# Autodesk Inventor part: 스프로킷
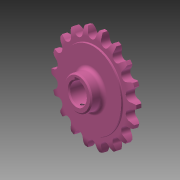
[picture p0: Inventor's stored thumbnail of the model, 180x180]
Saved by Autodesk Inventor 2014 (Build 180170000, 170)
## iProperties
Created: 2016-03
Part Number: 스프로킷
Material: 강철, 탄소
Document SubType Name: Modeling
Designer: mduedu
Density: 7.87 g/cm^3
Mass: 301.818 g
Surface Area: 124.882 cm^2
Volume: 38.3505 cm^3
Appearance: Pink
Author: mduedu
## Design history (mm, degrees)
sketch "스케치1"
  geometry: L1 (0, 5)-(29.5, 5); L2 (29.5, 5)-(29.5, 4.1); L3 (30, 3.6)-(33.625, 3.6); L4 (40, 2)-(40, 0); L5 (40, 0)-(0, 0); L6 (0, 0)-(0, 5); L7 (0, -5)-(29.5, -5); L8 (29.5, -5)-(29.5, -4.1); L9 (30, -3.6)-(33.625, -3.6); L10 (40, -2)-(40, 0); L11 (0, 0)-(0, -5); A1 r 13.5 centre (33.625, -9.9) between (40, 2) and (33.625, 3.6); A2 r 13.5 centre (33.625, 9.9) between (33.625, -3.6) and (40, -2); A3 r 0.5 centre (30, 4.1) between (29.5, 4.1) and (30, 3.6); A4 r 0.5 centre (30, -4.1) between (30, -3.6) and (29.5, -4.1); 2 further points
  constraints: 22 end point, 8 point on circle, 6 symmetric about line, 5 tangent, 4 centre point, 4 parallel, 4 point on line, 1 equal radius, 1 horizontal, 1 perpendicular, 1 other
  dimensions: "d0" = 80 diameter of L4 L6; "d2" = 59 diameter of L2 L6; "d3" = 1.6 vertical distance of L4.start L3.end; "d4" = 3.6 distance from line of L4.end L3; "d5" = 5 distance between parallel lines of L5 L1; "d6" = 13.5 radius of A1; "d15" = 0.5 radius of A3
revolve "회전1" sketch "스케치1" stored, may be unused: angle "d7" = 90 deg
sketch "스케치2" dims "d8" = 65.2, "d11" = 80
  geometry: L1 (0, 0)-(0, 32.6); A1 r 36.57 centre (0, 0) between (-16.231, 32.771) and (0, 36.57); A2 r 3.97 centre (0, 36.57) between (-3.866, 35.665) and (0, 32.6); A3 r 12.7 centre (-16.231, 32.771) between (-3.866, 35.665) and (-5.534, 39.615); A4 r 12.7 centre (16.231, 32.771) between (5.534, 39.615) and (3.866, 35.665); A5 r 3.97 centre (0, 36.57) between (0, 32.6) and (3.866, 35.665); A6 r 40 centre (0, 0) between (5.534, 39.615) and (-5.534, 39.615); 2 further points
  constraints: 12 point on circle, 6 centre point, 4 coincident, 3 symmetric about line, 2 end point, 1 point on line, 1 tangent, 1 vertical, 1 vertical alignment, 7 other
  dimensions: "d10" = 73.14 diameter of A1; "d12" = 12.7 radius of A3
extrude "돌출1" cut sketch "스케치2" stored distance "d13" = 10; taper "d14" = 0 deg
sketch "스케치3"
  geometry: C1 r 13 at (0, 0); 1 further point
  constraints: 1 centre point, 1 coincident
  dimensions: "d19" = 26 diameter of C1
extrude "돌출2" join sketch "스케치3" distance "d20" = 10; taper "d21" = 0 deg
fillet "모깎기1" dims "d22" = 3
sketch "스케치4"
  geometry: L1 (-2.5, 0)-(2.5, 0); L2 (2.5, 0)-(2.5, 10.3); L3 (2.5, 10.3)-(-2.5, 10.3); L4 (-2.5, 10.3)-(-2.5, 0); C1 r 8 at (0, 0); 2 further points
  constraints: 8 end point, 2 coincident, 2 parallel, 1 centre point, 1 horizontal, 1 midpoint, 1 perpendicular
  dimensions: "d23" = 16 diameter of C1; "d25" = 5 distance of L2.end L3.end; "d26" = 10.3 distance of L1.end L2.end
extrude "돌출3" cut sketch "스케치4" stored distance "d27" = 8; taper "d28" = 0 deg
chamfer "모따기2" distance "d42" = 1; stored, may be unused: second distance "d43" = 2, angle "d44" = 45 deg
node "작업 평면2"
sketch "스케치6"
  geometry: L1 (-12, 15)-(12, 15) reference; 2 further points
  constraints: 1 vertical alignment
  dimensions: "d59" = 4 distance from line of point (0.008, 11) L1
hole "구멍2" sketch "스케치6" at (0.008, 11) diameter "d48" = 3; stored, may be unused: countersink angle "d52" = 90 deg, drill point angle "d54" = 118 deg; dims "d49" = 6, "d50" = 4, "d51" = 2, "d53" = 8
thread "Thread1" dims "d56" = 10, "d57" = 0
node "솔리드1"
pattern_circular "원형 패턴1" dims angle "d17" = 360 deg
other parameters: "d55" = -13
